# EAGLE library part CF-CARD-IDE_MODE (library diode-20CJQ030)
Hirose Compact Flash Adapter Type I or II without Eject Button
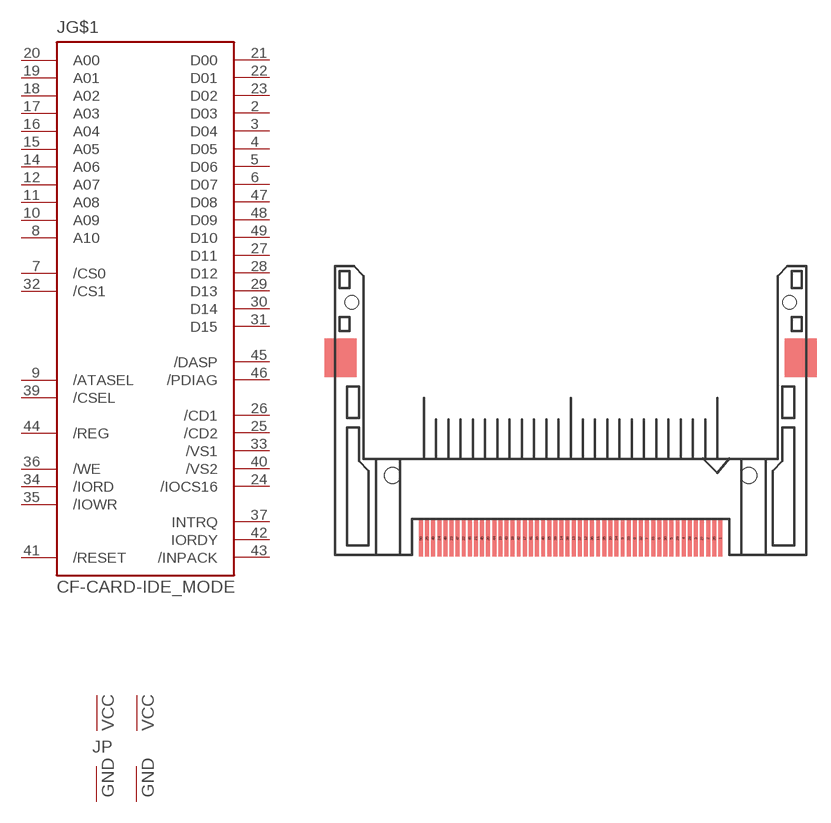
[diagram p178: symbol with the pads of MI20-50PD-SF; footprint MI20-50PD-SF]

Designator prefix J; gates G$1=MI20-50PD-SF-IDE_MODE P=PWR

## CF-CARD-IDE_MODE  [MI20-50PD-SF]
1  P:GND1  pwr
2  G$1:D03
3  G$1:D04
4  G$1:D05
5  G$1:D06
6  G$1:D07
7  G$1:/CS0  in
8  G$1:A10  in
9  G$1:/ATASEL  in
10  G$1:A09  in
11  G$1:A08  in
12  G$1:A07  in
13  P:VCC2  pwr
14  G$1:A06  in
15  G$1:A05  in
16  G$1:A04  in
17  G$1:A03  in
18  G$1:A02  in
19  G$1:A01  in
20  G$1:A00  in
21  G$1:D00
22  G$1:D01
23  G$1:D02
24  G$1:/IOCS16  out
25  G$1:/CD2  out
26  G$1:/CD1  out
27  G$1:D11
28  G$1:D12
29  G$1:D13
30  G$1:D14
31  G$1:D15
32  G$1:/CS1  in
33  G$1:/VS1  out
34  G$1:/IORD  in
35  G$1:/IOWR  in
36  G$1:/WE  in
37  G$1:INTRQ  out
38  P:VCC1  pwr
39  G$1:/CSEL  in
40  G$1:/VS2  out
41  G$1:/RESET  in
42  G$1:IORDY  out
43  G$1:/INPACK  out
44  G$1:/REG  in
45  G$1:/DASP
46  G$1:/PDIAG
47  G$1:D08
48  G$1:D09
49  G$1:D10
50  P:GND2  pwr

## Footprint MI20-50PD-SF (pad centres in mm)
Hirose Compact Flash Adapter Type I or II without Eject Button
smd 0.41 x 3.75: 1 15.557,-18.78; 2 14.287,-18.78; 3 13.018,-18.78; 4 11.748,-18.78; 5 10.477,-18.78; 6 9.207,-18.78; 7 7.938,-18.78; 8 6.668,-18.78; 9 5.397,-18.78; 10 4.128,-18.78; 11 2.857,-18.78; 12 1.587,-18.78; 13 0.318,-18.78; 14 -0.953,-18.78; 15 -2.223,-18.78; 16 -3.493,-18.78; 17 -4.763,-18.78; 18 -6.032,-18.78; 19 -7.303,-18.78; 20 -8.572,-18.78; 21 -9.842,-18.78; 22 -11.113,-18.78; 23 -12.383,-18.78; 24 -13.652,-18.78; 25 -14.922,-18.78; 26 14.922,-18.78; 27 13.652,-18.78; 28 12.383,-18.78; 29 11.113,-18.78; 30 9.842,-18.78; 31 8.572,-18.78; 32 7.303,-18.78; 33 6.032,-18.78; 34 4.763,-18.78; 35 3.493,-18.78; 36 2.223,-18.78; 37 0.953,-18.78; 38 -0.318,-18.78; 39 -1.587,-18.78; 40 -2.857,-18.78; 41 -4.128,-18.78; 42 -5.397,-18.78; 43 -6.668,-18.78; 44 -7.938,-18.78; 45 -9.207,-18.78; 46 -10.477,-18.78; 47 -11.748,-18.78; 48 -13.018,-18.78; 49 -14.287,-18.78; 50 -15.557,-18.78
hole 1.676 at 18.5,-12.25
hole 1.676 at -18.5,-12.25
hole 1.422 at -22.75,5.75
hole 1.422 at 22.75,5.75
